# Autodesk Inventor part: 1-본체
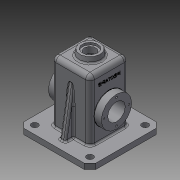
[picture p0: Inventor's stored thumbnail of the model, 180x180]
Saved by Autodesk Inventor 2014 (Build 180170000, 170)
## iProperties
Created: 2016-02
Part Number: 1-본체
Material: 일반
Document SubType Name: Modeling
Designer: J.H.CHAE
Density: 1 g/cm^3
Appearance: 기본값
Author: J.H.CHAE
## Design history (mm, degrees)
sketch "스케치1"
  geometry: L1 (-65, -65)-(65, -65); L2 (65, -65)-(65, 65); L3 (65, 65)-(-65, 65); L4 (-65, 65)-(-65, -65); 1 further point
  constraints: 8 end point, 2 parallel, 1 horizontal, 1 perpendicular
  dimensions: "d0" = 130 distance of L3.end L1.start; "d1" = 130 distance of L1.start L1.end; "d2" = 65 distance from line of L3 point (0, 0) (= 0.5 x d0); "d3" = 65 distance from line of L4 point (0, 0) (= 0.5 x d1)
extrude "돌출1" new body sketch "스케치1" distance "d4" = 10; taper "d5" = 0 deg
sketch "스케치2"
  geometry: L1 (35, 120)-(-35, 120); L2 (-35, 120)-(-35, 10); L3 (-35, 10)-(35, 10); L4 (35, 10)-(35, 120); L5 (-65, 0)-(65, 0) reference; L6 (-65, 10)-(65, 10) reference; 2 further points
  constraints: 8 end point, 2 midpoint, 2 parallel, 1 horizontal, 1 perpendicular
  dimensions: "d6" = 120 distance between parallel lines of L5 L1; "d7" = 70 distance of L1.start L1.end
extrude "돌출2" join sketch "스케치2" stored distance "d8" = 70; taper "d9" = 0 deg
sketch "스케치7"
  geometry: L1 (10, -30)-(10, 100) reference; C1 r 27.5 at (-45, 35); 2 further points
  constraints: 1 centre point, 1 horizontal alignment, 1 midpoint
  dimensions: "d28" = 55 distance from line of L1 C1.centre; "d29" = 55 diameter of C1
extrude "돌출6" join sketch "스케치7" distance "d30" = 13; taper "d31" = 0 deg
sketch "스케치5"
  geometry: L1 (-65, 0)-(-65, 10) reference; L2 (-65, 10)-(-35, 10) reference; L3 (-35, 10)-(-35, 27.5) reference; L4 (-35, 82.5)-(-35, 120) reference; L5 (-35, 120)-(35, 120) reference; L6 (35, 120)-(35, 10) reference; L7 (35, 10)-(65, 10) reference; L8 (65, 10)-(65, 0) reference; L9 (65, 0)-(-65, 0) reference; L10 (-30, 0)-(-30, 115); L11 (-30, 115)-(30, 115); L12 (30, 115)-(30, 0); L13 (-35, 27.5)-(-48, 27.5) reference; L14 (-48, 27.5)-(-48, 82.5) reference; L15 (-48, 82.5)-(-35, 82.5) reference; 1 further point
  constraints: 6 end point, 2 point on line, 2 other
  dimensions: "d14" = 5 distance between parallel lines of L6 L12
extrude "돌출4" cut sketch "스케치5" stored distance "d15" = 60; taper "d16" = 0 deg
sketch "스케치6"
  geometry: C1 r 27.5 at (55, 30) reference; 1 further point
extrude "돌출5" join sketch "스케치6" distance "d17" = 7; taper "d18" = -45 deg
hole "구멍1" diameter "d21" = 32; stored, may be unused: countersink angle "d25" = 90 deg, drill point angle "d27" = 118 deg; dims "d22" = 6, "d23" = 4, "d24" = 2, "d26" = 8, "d32" = 10, "d33" = 10
sketch "스케치8"
  geometry: C1 r 20 at (35, -35); 1 further point
  constraints: 1 centre point, 1 coincident
  dimensions: "d34" = 40 diameter of C1
extrude "돌출7" join sketch "스케치8" distance "d35" = 10; taper "d36" = -10 deg
hole "구멍2" diameter "d39" = 21; stored, may be unused: countersink angle "d43" = 90 deg, drill point angle "d45" = 118 deg; dims "d37" = 10, "d38" = 10, "d40" = 6, "d41" = 28, "d42" = 4, "d44" = 8
sketch "스케치10"
  geometry: L1 (50, 10)-(35, 95.069); L2 (65, 10)-(-65, 10) reference; L3 (65, 0)-(65, 10) reference; L4 (35, 10)-(35, 120) reference; 1 further point
  constraints: 2 end point, 2 point on line
  dimensions: "d46" = 15 distance from line of L3 L1.start; "d47" = 10 deg angle of L1 L3
feature "리브1" sketch "스케치10" dims "d48" = 1, "d49" = 10, "d50" = 0, "d51" = 0, "d52" = 1, "d53" = 1
sketch "스케치11"
  geometry: C1 r 16 at (0, 0) reference; 2 further points
  constraints: 1 horizontal alignment
  dimensions: "d54" = 22.5 distance of C1.centre point (-22.5, 0)
hole "구멍3" sketch "스케치11" at (-22.5, 0) diameter "d55" = 3.242; stored, may be unused: countersink angle "d59" = 90 deg, drill point angle "d61" = 118 deg; dims "d56" = 8, "d57" = 28, "d58" = 4, "d60" = 10
fillet "모깎기1" dims "d65" = 8
fillet "모깎기2" dims "d66" = 8
fillet "모깎기3" dims "d67" = 3
fillet "모깎기4" dims "d68" = 3
fillet "모깎기5" dims "d69" = 3
fillet "모깎기6" dims "d70" = 3
fillet "모깎기7" dims "d71" = 3
fillet "모깎기8" dims "d72" = 3
fillet "모깎기9" dims "d73" = 3
chamfer "모따기1" distance "d74" = 10; stored, may be unused: second distance "d75" = 2, angle "d76" = 45 deg
sketch "스케치12"
  geometry: L1 (50, -50)-(-50, -50); L2 (-50, -50)-(-50, 50); L3 (-50, 50)-(50, 50); L4 (50, 50)-(50, -50); 3 further points
  constraints: 8 end point, 2 midpoint, 2 parallel, 1 horizontal, 1 horizontal alignment, 1 perpendicular, 1 vertical alignment
  dimensions: "d77" = 100 distance of L1.start L1.end; "d78" = 100 distance of L1.end L2.end
hole "구멍4" sketch "스케치12" at (50, -50), (-50, 50), (-50, -50), (50, 50) diameter "d79" = 12; stored, may be unused: countersink angle "d83" = 90 deg, drill point angle "d85" = 118 deg; dims "d80" = 8, "d81" = 28, "d82" = 4, "d84" = 10
fillet "모깎기10" dims "d86" = 0.5
fillet "모깎기11" dims "d87" = 3
fillet "모깎기12" dims "d88" = 0.5
sketch "스케치13"
  geometry: L1 (9.312, 4.061)-(9.312, 49.939); L2 (9.312, 49.939)-(14.688, 49.939); L3 (14.688, 49.939)-(14.688, 4.061); L4 (14.688, 4.061)-(9.312, 4.061); L5 (-18, 8.763)-(-18, 45.237) reference; L6 (99, 62)-(0, 62) reference; 3 further points
  constraints: 2 midpoint, 1 vertical, 2 other
  dimensions: "d89" = 30 distance from line of L5 point (12, 4.061); "d90" = 35 distance from line of L6 point (9.312, 27)
feature "엠보싱1" sketch "스케치13" dims "d0" = 130, "d1" = 130, "d2" = 65 (= 0.5 x d0), "d3" = 65 (= 0.5 x d1), "d91" = 0.5, "d92" = 0
node "솔리드1"
mirror "대칭1"
mirror "대칭2"
pattern_circular "원형 패턴1" dims angle "d63" = 360 deg
mirror "대칭3"
node "절단 모서리 투영1"
